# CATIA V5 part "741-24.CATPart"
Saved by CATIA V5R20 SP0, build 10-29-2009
Part number: 741-24
Bounding box of the stored display mesh (mm): x -24 to 24.335, y -23.94 to 23.94, z -23 to 36
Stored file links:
  C:\Users\Utente\Desktop\IO LAVORO\3D X SITO CF\X SITO\741\741-24.CATPart
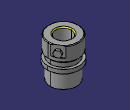
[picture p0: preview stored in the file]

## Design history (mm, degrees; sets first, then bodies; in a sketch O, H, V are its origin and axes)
Set1
  DatumSurface1 to DatumSurface42 "741-24"
Body1 (main body)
